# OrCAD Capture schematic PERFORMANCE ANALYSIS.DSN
size A
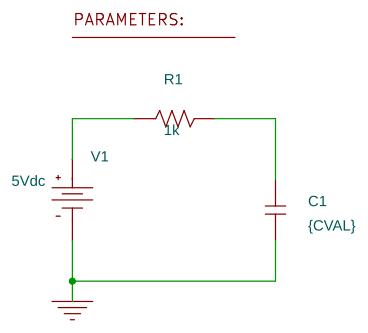
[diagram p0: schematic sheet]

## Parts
1  PARAM
C1  {CVAL}  [CK05]
R1  1k  [RC05]
V1  VDC

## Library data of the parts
1 = PARAM: CVAL: 1n
C1 = C: IC: 0
R1 = R
V1 = VDC: DC: 5Vdc

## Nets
0: C1.1 V1.1(-)
N00098: R1.1 V1.0(+)
N00105: C1.2 R1.2
